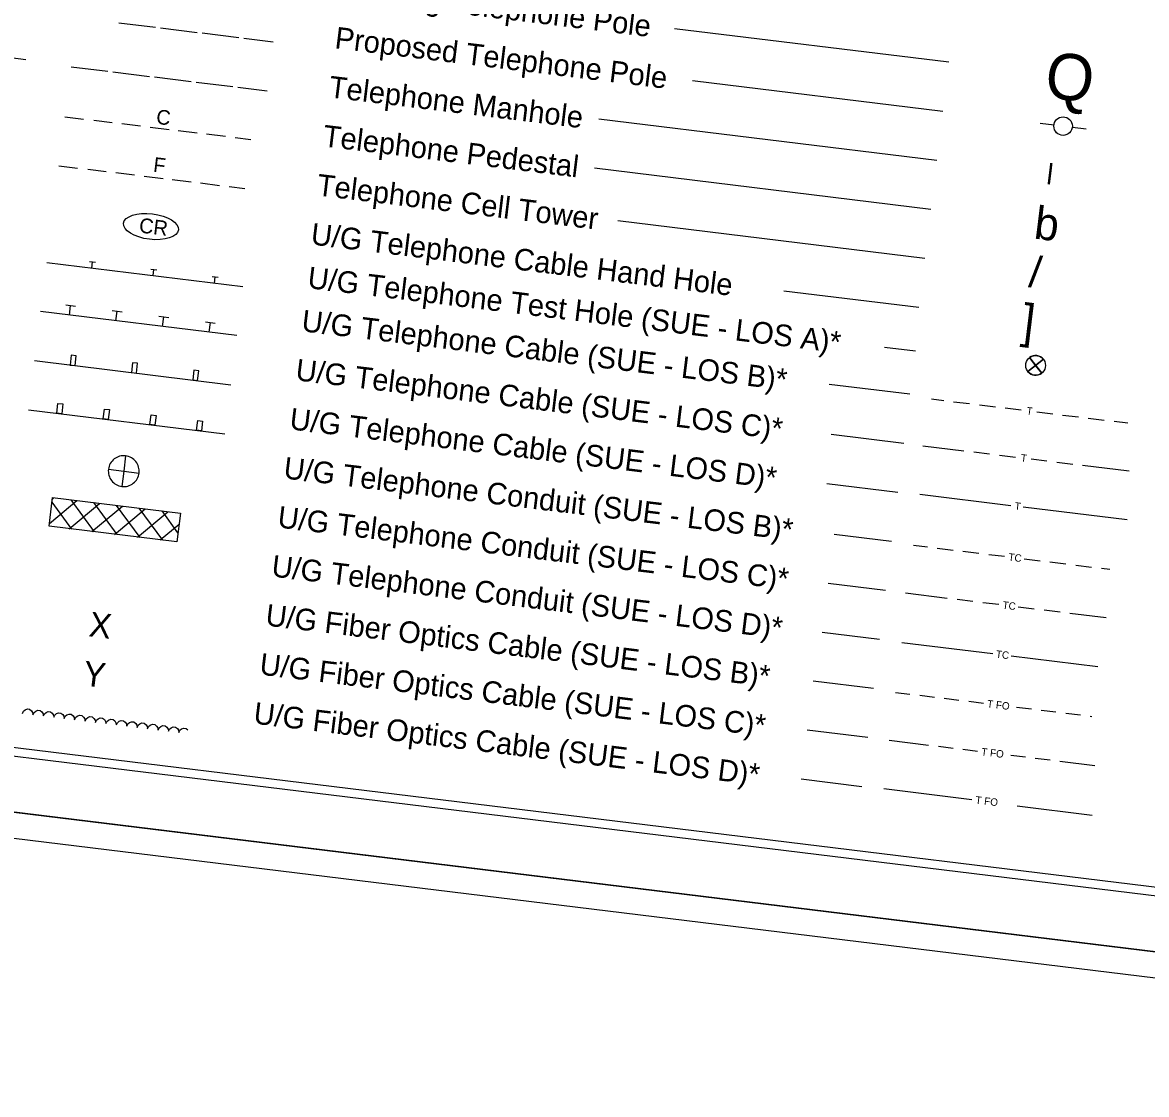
# Model space of a CAD drawing. Extents: x 1756435 to 1766932, y 416863 to 426859.
# Drawn here: x 1762075 to 1763894, y 416863 to 418599 of the extents above; entities that cross this region are included whole.
import ezdxf

# ---------------------------------------------------------------- set-up
doc = ezdxf.new("R2010")
doc.units = 0
for name, color, linetype in [('Exist Utilities Telephone Test Hole SUE LOS A CELL', 7, 'Continuous'), ('Prop WCC CELL', 7, 'Continuous'), ('Scratch_Level_2', 7, 'Continuous'), ('Sheet Cutting Line CELL', 7, 'Continuous'), ('Sheet Plot Border Inside CELL', 7, 'Continuous'), ('Sheet Plot Border Outside CELL', 7, 'Continuous'), ('Sheet Symbology CELL', 7, 'Continuous')]:
    doc.layers.add(name, color=color, linetype=linetype)

msp = doc.modelspace()

# ---------------------------------------------------------------- linework, layer by layer
at = {"layer": 'Exist Utilities Telephone Test Hole SUE LOS A CELL'}
for points in [[(1763727.5, 418053.6), (1763702.4, 418033.9), (1763714.9, 418043.7), (1763705.1, 418056.3), (1763724.8, 418031.1)], [(1763705.1, 418056.3), (1763714.9, 418043.7), (1763727.5, 418053.6)], [(1763724.8, 418031.1), (1763714.9, 418043.7), (1763702.4, 418033.9)]]:
    msp.add_lwpolyline(points, dxfattribs=at)
msp.add_circle((1763714.9, 418043.7), 16, dxfattribs=at)
for start, end in [(38.0234, 128.0234), (218.0234, 308.0234)]:
    msp.add_arc((1763714.9, 418043.7), 16, start, end, dxfattribs=at)
at = {"layer": 'Prop WCC CELL'}
msp.add_ellipse((1762282.7, 418268.5), major_axis=(44.5, -5.4), ratio=0.462467, dxfattribs=at)
at = {"layer": 'Scratch_Level_2'}
msp.add_lwpolyline([(1759243.8, 422098.1), (1765929.9, 421280), (1765395.5, 416912.5), (1758709.3, 417730.7)], close=True, dxfattribs=at)
at = {"layer": 'Sheet Cutting Line CELL'}
for p, q in [((1758709.3, 417730.7), (1765395.5, 416912.5)), ((1758704.3, 417689.2), (1765453.9, 416863.3))]:
    msp.add_line(p, q, dxfattribs=at)
at = {"layer": 'Sheet Plot Border Inside CELL'}
msp.add_lwpolyline([(1758771.9, 417813.5), (1765388.5, 417003.9), (1765901.1, 421193), (1759284.5, 422002.7)], close=True, dxfattribs=at)
at = {"layer": 'Sheet Plot Border Outside CELL'}
msp.add_lwpolyline([(1758709.3, 417730.7), (1765395.5, 416912.5), (1765929.9, 421280), (1759243.8, 422098.1)], close=True, dxfattribs=at)
at = {"layer": 'Sheet Symbology CELL'}
for p, q in [((1762080, 418538.6), (1761416.3, 418619.8)), ((1762230.5, 418598.4), (1762290.1, 418591.1)), ((1762298, 418590.2), (1762357.5, 418582.9)), ((1763574.6, 418534.4), (1763130.3, 418588.7)), ((1762365.5, 418581.9), (1762425, 418574.6)), ((1762433, 418573.6), (1762480.6, 418567.8)), ((1762153.3, 418527.3), (1762212.8, 418520)), ((1762220.8, 418519), (1762280.3, 418511.7)), ((1762288.3, 418510.8), (1762347.8, 418503.5)), ((1762355.8, 418502.5), (1762415.3, 418495.2)), ((1762423.3, 418494.2), (1762470.9, 418488.4)), ((1763564.8, 418455), (1763159.6, 418504.5)), ((1762143.3, 418446), (1762173.5, 418442.3)), ((1762220, 418436.6), (1762190, 418440.3)), ((1763555.1, 418375.5), (1763007.8, 418442.5)), ((1762265.6, 418431), (1762235.4, 418434.7)), ((1762312.3, 418425.3), (1762281.3, 418429.1)), ((1762357.7, 418419.7), (1762327, 418423.5)), ((1763744.7, 418432.9), (1763722.4, 418435.6)), ((1763774.5, 418429.2), (1763796.8, 418426.5)), ((1762403.6, 418414.1), (1762372.4, 418417.9)), ((1762444.5, 418409.1), (1762419.1, 418412.2)), ((1762133.6, 418366.6), (1762163.8, 418362.9)), ((1762210.2, 418357.2), (1762180.3, 418360.9)), ((1762255.9, 418351.6), (1762225.7, 418355.3)), ((1762302.6, 418345.9), (1762271.6, 418349.7)), ((1763545.4, 418296.1), (1763000.8, 418362.8)), ((1762348, 418340.3), (1762317.2, 418344.1)), ((1762393.9, 418334.7), (1762362.7, 418338.5)), ((1762434.8, 418329.7), (1762409.4, 418332.8)), ((1763535.7, 418216.7), (1763038.5, 418277.6)), ((1762113.9, 418210.2), (1762431.5, 418171.3)), ((1762183.1, 418211.8), (1762193, 418210.6)), ((1762186.9, 418201.3), (1762188.1, 418211.2)), ((1762282.4, 418199.6), (1762292.3, 418198.4)), ((1762286.1, 418189.1), (1762287.3, 418199)), ((1762381.6, 418187.5), (1762391.6, 418186.3)), ((1762385.4, 418177), (1762386.6, 418186.9)), ((1763526, 418137.3), (1763307.5, 418164.1)), ((1762421.8, 418091.9), (1762104.1, 418130.8)), ((1762144.7, 418141.7), (1762160.5, 418139.8)), ((1762150.7, 418125.1), (1762152.6, 418140.8)), ((1762220.1, 418132.5), (1762236, 418130.6)), ((1762226.1, 418115.9), (1762228, 418131.5)), ((1762295.5, 418123.3), (1762311.4, 418121.3)), ((1762301.6, 418106.6), (1762303.5, 418122.3)), ((1762371, 418114), (1762386.9, 418112.1)), ((1762377, 418097.4), (1762378.9, 418113.1)), ((1763520.6, 418066.7), (1763470.4, 418072.9)), ((1762094.4, 418051.4), (1762412, 418012.5)), ((1763511, 417996.9), (1763380.8, 418012.8)), ((1763546.4, 417989.4), (1763566.3, 417986.9)), ((1763582.2, 417985), (1763608, 417981.8)), ((1762084.7, 417972), (1762402.3, 417933.1)), ((1763623.9, 417979.9), (1763649.7, 417976.7)), ((1763665.6, 417974.8), (1763691.4, 417971.6)), ((1763716.8, 417968.5), (1763742.6, 417965.3)), ((1763758.5, 417963.4), (1763784.3, 417960.2)), ((1763800.2, 417958.3), (1763826, 417955.1)), ((1763841.9, 417953.2), (1763864, 417950.5)), ((1763501.3, 417917.5), (1763383.7, 417931.9)), ((1763532.1, 417913.7), (1763598.7, 417905.6)), ((1762241.7, 417897.3), (1762238.7, 417872.5)), ((1763614.6, 417903.6), (1763640.4, 417900.5)), ((1763656.3, 417898.5), (1763682.1, 417895.4)), ((1763707.5, 417892.3), (1763733.3, 417889.1)), ((1762213.8, 417875.5), (1762238.7, 417872.5)), ((1763749.2, 417887.2), (1763775, 417884)), ((1763790.9, 417882.1), (1763866.5, 417872.8)), ((1762238.7, 417872.5), (1762235.6, 417847.7)), ((1762238.7, 417872.5), (1762263.5, 417869.4)), ((1763491.6, 417838.1), (1763377, 417852.1)), ((1762117.8, 417783.2), (1762123.5, 417829.7)), ((1762118.4, 417787.8), (1762162.6, 417824.9)), ((1762154.5, 417778.7), (1762122.6, 417822.5)), ((1762123.2, 417827.3), (1762125.7, 417829.4)), ((1762123.5, 417829.7), (1762330.4, 417804.3)), ((1762150.2, 417779.2), (1762199.5, 417820.3)), ((1762191.5, 417774.2), (1762153.5, 417826)), ((1762228.2, 417769.7), (1762190.4, 417821.5)), ((1763527.5, 417835.1), (1763674.9, 417817.1)), ((1762186.9, 417774.7), (1762236.5, 417815.8)), ((1762223.8, 417770.2), (1762273.2, 417811.3)), ((1762265.1, 417765.2), (1762227.1, 417817)), ((1762260.8, 417765.7), (1762309.9, 417806.8)), ((1762302, 417760.7), (1762263.9, 417812.5)), ((1762326.5, 417772.8), (1762300.8, 417808)), ((1762330.4, 417804.3), (1762324.7, 417757.9)), ((1763694.8, 417814.6), (1763863, 417794)), ((1762324.7, 417757.9), (1762117.8, 417783.2)), ((1762297.5, 417761.2), (1762328.2, 417786.9)), ((1763481.8, 417758.7), (1763388.7, 417770.1)), ((1763517.4, 417752.6), (1763539.6, 417749.9)), ((1763555.5, 417747.9), (1763581.3, 417744.8)), ((1763597.2, 417742.8), (1763623, 417739.7)), ((1763638.9, 417737.7), (1763664.7, 417734.6)), ((1763696.4, 417730.7), (1763722.2, 417727.5)), ((1763738.1, 417725.6), (1763763.9, 417722.4)), ((1763779.8, 417720.5), (1763805.6, 417717.3)), ((1763821.5, 417715.4), (1763835, 417713.7)), ((1763472.1, 417679.3), (1763379, 417690.7)), ((1763504.1, 417675.4), (1763571.8, 417667.1)), ((1763587.7, 417665.1), (1763613.5, 417662)), ((1763629.4, 417660), (1763655.2, 417656.9)), ((1763686.9, 417653), (1763712.7, 417649.8)), ((1763728.6, 417647.9), (1763754.4, 417644.7)), ((1763770.3, 417642.8), (1763829.3, 417635.6)), ((1763462.4, 417599.9), (1763369.3, 417611.3)), ((1763498.2, 417595.3), (1763645.4, 417577.3)), ((1763675.2, 417573.6), (1763815.8, 417556.4)), ((1763452.7, 417520.5), (1763354.9, 417532.4)), ((1763488.3, 417514.4), (1763511.4, 417511.5)), ((1763527.3, 417509.6), (1763551.1, 417506.7)), ((1763567, 417504.7), (1763590.8, 417501.8)), ((1763606.7, 417499.9), (1763630.5, 417496.9)), ((1762074.8, 417480.2), (1762076.5, 417483.8)), ((1762076.5, 417483.8), (1762079.2, 417486.1)), ((1762079.2, 417486.1), (1762082.6, 417487.5)), ((1762082.6, 417487.5), (1762086.3, 417487.1)), ((1762086.3, 417487.1), (1762089.3, 417484.7)), ((1762089.3, 417484.7), (1762091.1, 417481.8)), ((1762091.1, 417481.8), (1762091.5, 417478.4)), ((1762091.7, 417478.2), (1762093.4, 417481.8)), ((1762093.4, 417481.8), (1762096.1, 417484.1)), ((1762096.1, 417484.1), (1762099.4, 417485.5)), ((1762099.4, 417485.5), (1762103.2, 417485)), ((1762103.2, 417485), (1762106.2, 417482.6)), ((1762106.2, 417482.6), (1762108, 417479.8)), ((1762108, 417479.8), (1762108.4, 417476.3)), ((1762108.6, 417476.1), (1762110.2, 417479.7)), ((1762110.2, 417479.7), (1762112.9, 417482)), ((1762112.9, 417482), (1762116.3, 417483.4)), ((1762116.3, 417483.4), (1762120.1, 417482.9)), ((1762120.1, 417482.9), (1762123, 417480.6)), ((1762123, 417480.6), (1762124.9, 417477.7)), ((1762124.9, 417477.7), (1762125.3, 417474.2)), ((1762125.4, 417474), (1762127.1, 417477.6)), ((1762127.1, 417477.6), (1762129.8, 417479.9)), ((1762129.8, 417479.9), (1762133.2, 417481.3)), ((1762133.2, 417481.3), (1762137, 417480.9)), ((1762137, 417480.9), (1762139.9, 417478.5)), ((1762139.9, 417478.5), (1762141.8, 417475.7)), ((1762141.8, 417475.7), (1762142.1, 417472.2)), ((1762142.3, 417472), (1762144, 417475.6)), ((1762144, 417475.6), (1762146.7, 417477.9)), ((1762146.7, 417477.9), (1762150.1, 417479.3)), ((1762150.1, 417479.3), (1762153.8, 417478.8)), ((1762153.8, 417478.8), (1762156.8, 417476.4)), ((1762156.8, 417476.4), (1762158.6, 417473.6)), ((1762158.6, 417473.6), (1762159, 417470.1)), ((1762159.2, 417469.9), (1762160.8, 417473.5)), ((1762160.8, 417473.5), (1762163.5, 417475.8)), ((1762163.5, 417475.8), (1762166.9, 417477.2)), ((1762166.9, 417477.2), (1762170.7, 417476.7)), ((1762170.7, 417476.7), (1762173.6, 417474.4)), ((1762173.6, 417474.4), (1762175.5, 417471.5)), ((1762177.7, 417471.5), (1762180.4, 417473.7)), ((1762180.4, 417473.7), (1762183.8, 417475.1)), ((1762183.8, 417475.1), (1762187.6, 417474.7)), ((1762187.6, 417474.7), (1762190.5, 417472.3)), ((1763684.1, 417490.4), (1763708, 417487.5)), ((1763723.9, 417485.5), (1763747.7, 417482.6)), ((1763763.6, 417480.7), (1763787.4, 417477.8)), ((1763803.3, 417475.8), (1763805.9, 417475.5)), ((1762175.5, 417471.5), (1762175.9, 417468.1)), ((1762176.1, 417467.8), (1762177.7, 417471.5)), ((1762190.5, 417472.3), (1762192.4, 417469.5)), ((1762192.4, 417469.5), (1762192.8, 417466)), ((1762192.9, 417465.8), (1762194.6, 417469.4)), ((1762194.6, 417469.4), (1762197.3, 417471.7)), ((1762197.3, 417471.7), (1762200.7, 417473.1)), ((1762200.7, 417473.1), (1762204.5, 417472.6)), ((1762204.5, 417472.6), (1762207.4, 417470.2)), ((1762207.4, 417470.2), (1762209.3, 417467.4)), ((1762209.3, 417467.4), (1762209.6, 417463.9)), ((1762209.8, 417463.7), (1762211.5, 417467.3)), ((1762211.5, 417467.3), (1762214.2, 417469.6)), ((1762214.2, 417469.6), (1762217.6, 417471)), ((1762217.6, 417471), (1762221.3, 417470.5)), ((1762221.3, 417470.5), (1762224.3, 417468.2)), ((1762224.3, 417468.2), (1762226.1, 417465.3)), ((1762226.1, 417465.3), (1762226.5, 417461.9)), ((1762226.7, 417461.6), (1762228.3, 417465.3)), ((1762228.3, 417465.3), (1762231, 417467.5)), ((1762231, 417467.5), (1762234.4, 417468.9)), ((1762234.4, 417468.9), (1762238.2, 417468.5)), ((1762238.2, 417468.5), (1762241.1, 417466.1)), ((1762241.1, 417466.1), (1762243, 417463.3)), ((1762243, 417463.3), (1762243.4, 417459.8)), ((1762243.6, 417459.6), (1762245.2, 417463.2)), ((1762245.2, 417463.2), (1762247.9, 417465.5)), ((1762247.9, 417465.5), (1762251.3, 417466.9)), ((1762251.3, 417466.9), (1762255.1, 417466.4)), ((1762255.1, 417466.4), (1762258, 417464)), ((1762258, 417464), (1762259.9, 417461.2)), ((1762259.9, 417461.2), (1762260.3, 417457.7)), ((1762260.4, 417457.5), (1762262.1, 417461.1)), ((1762262.1, 417461.1), (1762264.8, 417463.4)), ((1762264.8, 417463.4), (1762268.2, 417464.8)), ((1762268.2, 417464.8), (1762272, 417464.4)), ((1762272, 417464.4), (1762274.9, 417462)), ((1762274.9, 417462), (1762276.8, 417459.1)), ((1762276.8, 417459.1), (1762277.1, 417455.7)), ((1762277.3, 417455.4), (1762279, 417459.1)), ((1762279, 417459.1), (1762281.7, 417461.4)), ((1762281.7, 417461.4), (1762285.1, 417462.8)), ((1762285.1, 417462.8), (1762288.8, 417462.3)), ((1762288.8, 417462.3), (1762291.8, 417459.9)), ((1762291.8, 417459.9), (1762293.6, 417457.1)), ((1762293.6, 417457.1), (1762294, 417453.6)), ((1762294.2, 417453.4), (1762295.8, 417457)), ((1762295.8, 417457), (1762298.5, 417459.3)), ((1762298.5, 417459.3), (1762301.9, 417460.7)), ((1762301.9, 417460.7), (1762305.7, 417460.2)), ((1762305.7, 417460.2), (1762308.6, 417457.9)), ((1762308.6, 417457.9), (1762310.5, 417455)), ((1762310.5, 417455), (1762310.9, 417451.5)), ((1762312.7, 417454.9), (1762315.4, 417457.2)), ((1762315.4, 417457.2), (1762318.8, 417458.6)), ((1762318.8, 417458.6), (1762322.6, 417458.2)), ((1762322.6, 417458.2), (1762325.5, 417455.8)), ((1762325.5, 417455.8), (1762327.4, 417452.9)), ((1762329.6, 417452.9), (1762332.3, 417455.2)), ((1762332.3, 417455.2), (1762335.7, 417456.6)), ((1762335.7, 417456.6), (1762339.5, 417456.1)), ((1762339.5, 417456.1), (1762342.4, 417453.7)), ((1762311.1, 417451.3), (1762312.7, 417454.9)), ((1762327.4, 417452.9), (1762327.8, 417449.5)), ((1762327.9, 417449.2), (1762329.6, 417452.9)), ((1762342.4, 417453.7), (1762342.6, 417453.5)), ((1763443, 417441.1), (1763345.2, 417453)), ((1763478, 417436.8), (1763541.6, 417429)), ((1763557.5, 417427), (1763581.3, 417424.1)), ((1763597.2, 417422.2), (1763621, 417419.3)), ((1763674.6, 417412.7), (1763698.5, 417409.8)), ((1763714.3, 417407.8), (1763738.2, 417404.9)), ((1763754.1, 417403), (1763810.9, 417396)), ((1763433.3, 417361.6), (1763335.5, 417373.6)), ((1763469.2, 417358.6), (1763611.6, 417341.1)), ((1763684.9, 417330.6), (1763806.5, 417315.7))]:
    msp.add_line(p, q, dxfattribs=at)
for points in [[(1765850.3, 421189), (1759894.7, 421917.7), (1759385, 417752.9), (1765340.6, 417024.1)], [(1762151.9, 418044.3), (1762159.8, 418043.4), (1762161.8, 418059.3), (1762153.8, 418060.2)], [(1762251.1, 418032.2), (1762259.1, 418031.2), (1762261, 418047.1), (1762253.1, 418048.1)], [(1762350.4, 418020.1), (1762358.3, 418019.1), (1762360.3, 418035), (1762352.4, 418035.9)], [(1762132.2, 417982.3), (1762140.1, 417981.3), (1762138.2, 417965.4), (1762130.2, 417966.4)], [(1762207.6, 417973.1), (1762215.5, 417972.1), (1762213.6, 417956.2), (1762205.6, 417957.2)], [(1762283, 417963.8), (1762291, 417962.8), (1762289, 417947), (1762281.1, 417947.9)], [(1762358.5, 417954.6), (1762366.4, 417953.6), (1762364.5, 417937.7), (1762356.5, 417938.7)]]:
    msp.add_lwpolyline(points, close=True, dxfattribs=at)
msp.add_circle((1763759.4, 418431.1), 15, dxfattribs=at)
for start, end in [(83.0178, 173.0223), (353.0178, 83.0223), (173.0178, 263.0223), (263.0178, 353.0223)]:
    msp.add_arc((1762238.7, 417872.5), 25, start, end, dxfattribs=at)

# ---------------------------------------------------------------- texts
at = {"layer": 'Prop WCC CELL'}
msp.add_text('CR', height=24, rotation=353.0234, dxfattribs=at).set_placement((1762262.5, 418259))
at = {"layer": 'Sheet Symbology CELL'}
for s, height, p in [('Existing Telephone Pole', 35, (1762588.8, 418636.7)), ('Proposed Telephone Pole', 35, (1762579.1, 418557.3)), ('Q', 75, (1763727.4, 418477.9)), ('Telephone Manhole', 35, (1762569.4, 418477.9)), ('C', 23.7, (1762290.3, 418435)), ('Telephone Pedestal', 35, (1762559.7, 418398.5)), ('F', 23.7, (1762285.6, 418357.5)), ('l', 33, (1763731.3, 418337.4)), ('Telephone Cell Tower', 35, (1762550, 418319.1)), ('b', 52.8, (1763710.6, 418249.3)), ('U/G Telephone Cable Hand Hole', 35, (1762540.3, 418239.7)), ('/', 50, (1763702.4, 418171.1)), ('U/G Telephone Test Hole (SUE - LOS A)*', 35, (1762535, 418169.1)), ('U/G Telephone Cable (SUE - LOS B)*', 35, (1762525.3, 418099.2)), (']', 54, (1763690.5, 418090)), ('U/G Telephone Cable (SUE - LOS C)*', 35, (1762515.6, 418019.8)), ('U/G Telephone Cable (SUE - LOS D)*', 35, (1762505.9, 417940.4)), ('T', 12, (1763699.6, 417964.6)), ('U/G Telephone Conduit (SUE - LOS B)*', 35, (1762496.2, 417861)), ('T', 12, (1763690.3, 417888.3)), ('T', 12, (1763680.3, 417810.4)), ('U/G Telephone Conduit (SUE - LOS C)*', 35, (1762486.5, 417781.6)), ('U/G Telephone Conduit (SUE - LOS D)*', 35, (1762476.7, 417702.2)), ('TC', 12, (1763670.3, 417727.9)), ('U/G Fiber Optics Cable (SUE - LOS B)*', 35, (1762467, 417622.8)), ('TC', 12, (1763660.8, 417650.1)), ('X', 40, (1762180.9, 417605.3)), ('TC', 12, (1763650, 417570.7)), ('Y', 40, (1762171.2, 417525.9)), ('U/G Fiber Optics Cable (SUE - LOS C)*', 35, (1762457.3, 417543.4)), ('U/G Fiber Optics Cable (SUE - LOS D)*', 35, (1762447.6, 417464)), ('T FO', 12, (1763635.8, 417490.3)), ('T FO', 12, (1763626.3, 417412.6)), ('T FO', 12, (1763616.9, 417334.5))]:
    msp.add_text(s, height=height, rotation=353.0234, dxfattribs=at).set_placement(p)

doc.saveas('drawing.dxf')
